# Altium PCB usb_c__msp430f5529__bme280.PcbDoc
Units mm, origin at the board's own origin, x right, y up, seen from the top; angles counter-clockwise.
Board outline 82 x 52 mm, 2 copper layers (Top, Bottom), stack 0 mm thick; 30 components, 24 nets, 182 pads, 58 vias.
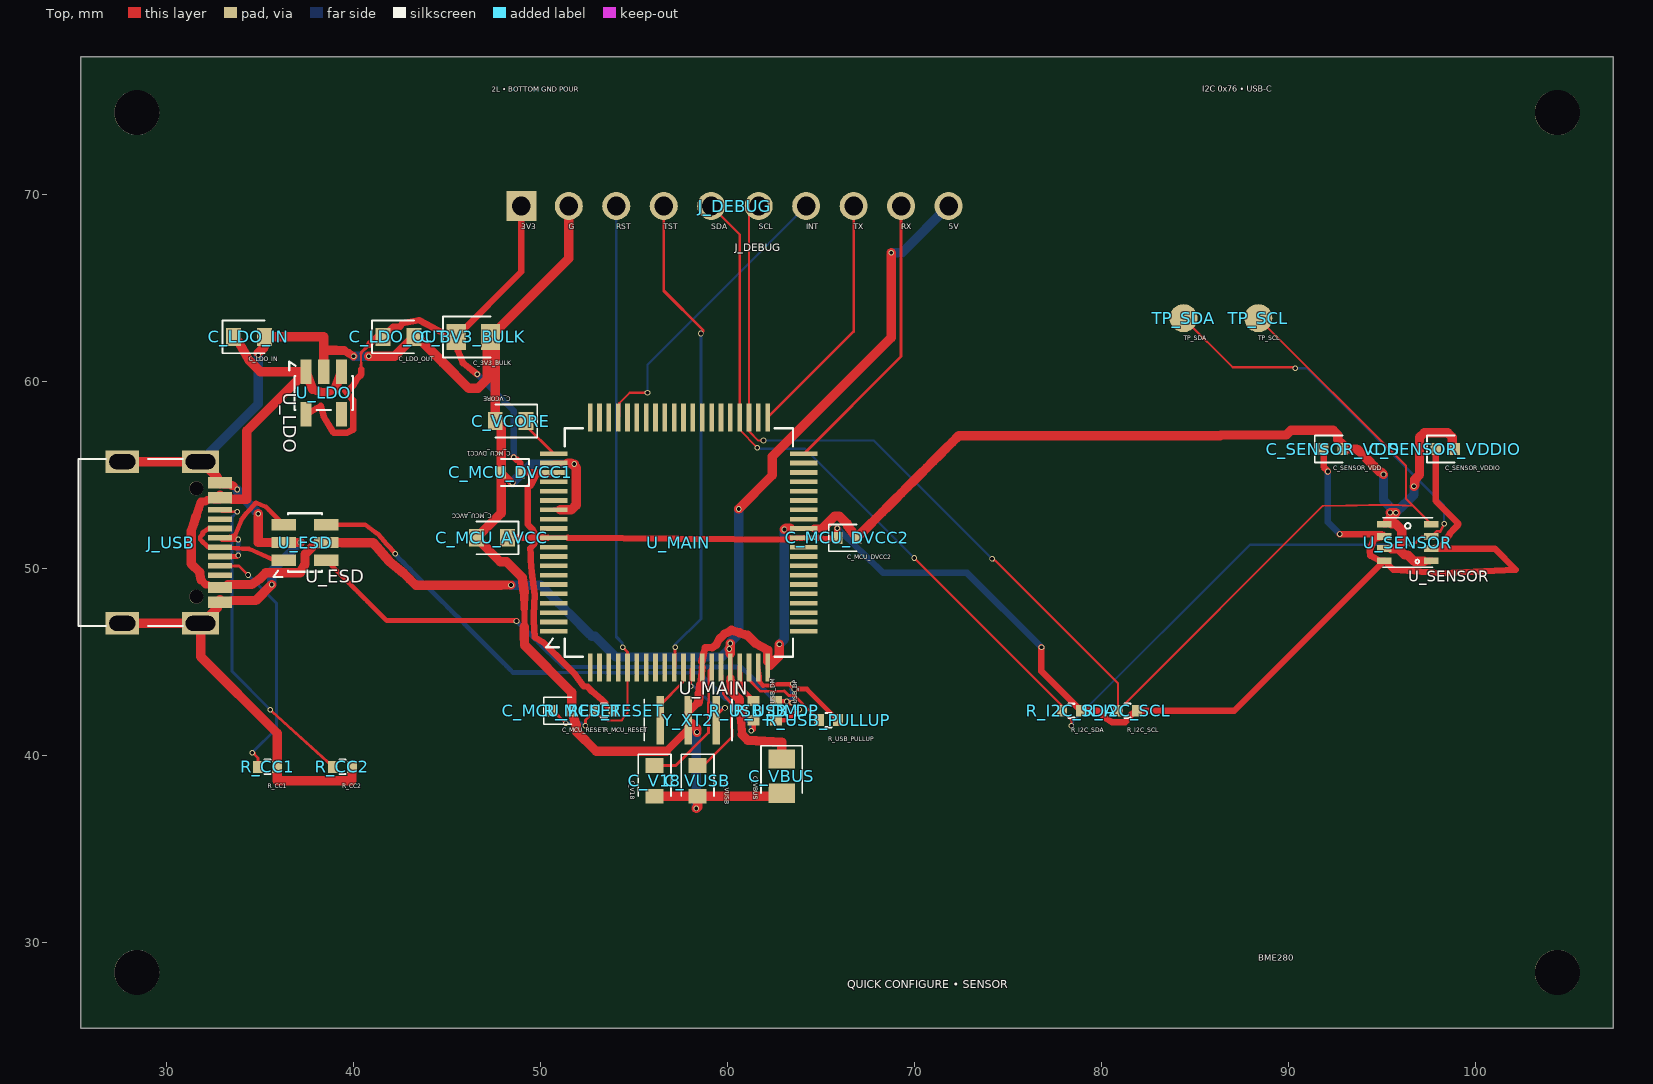
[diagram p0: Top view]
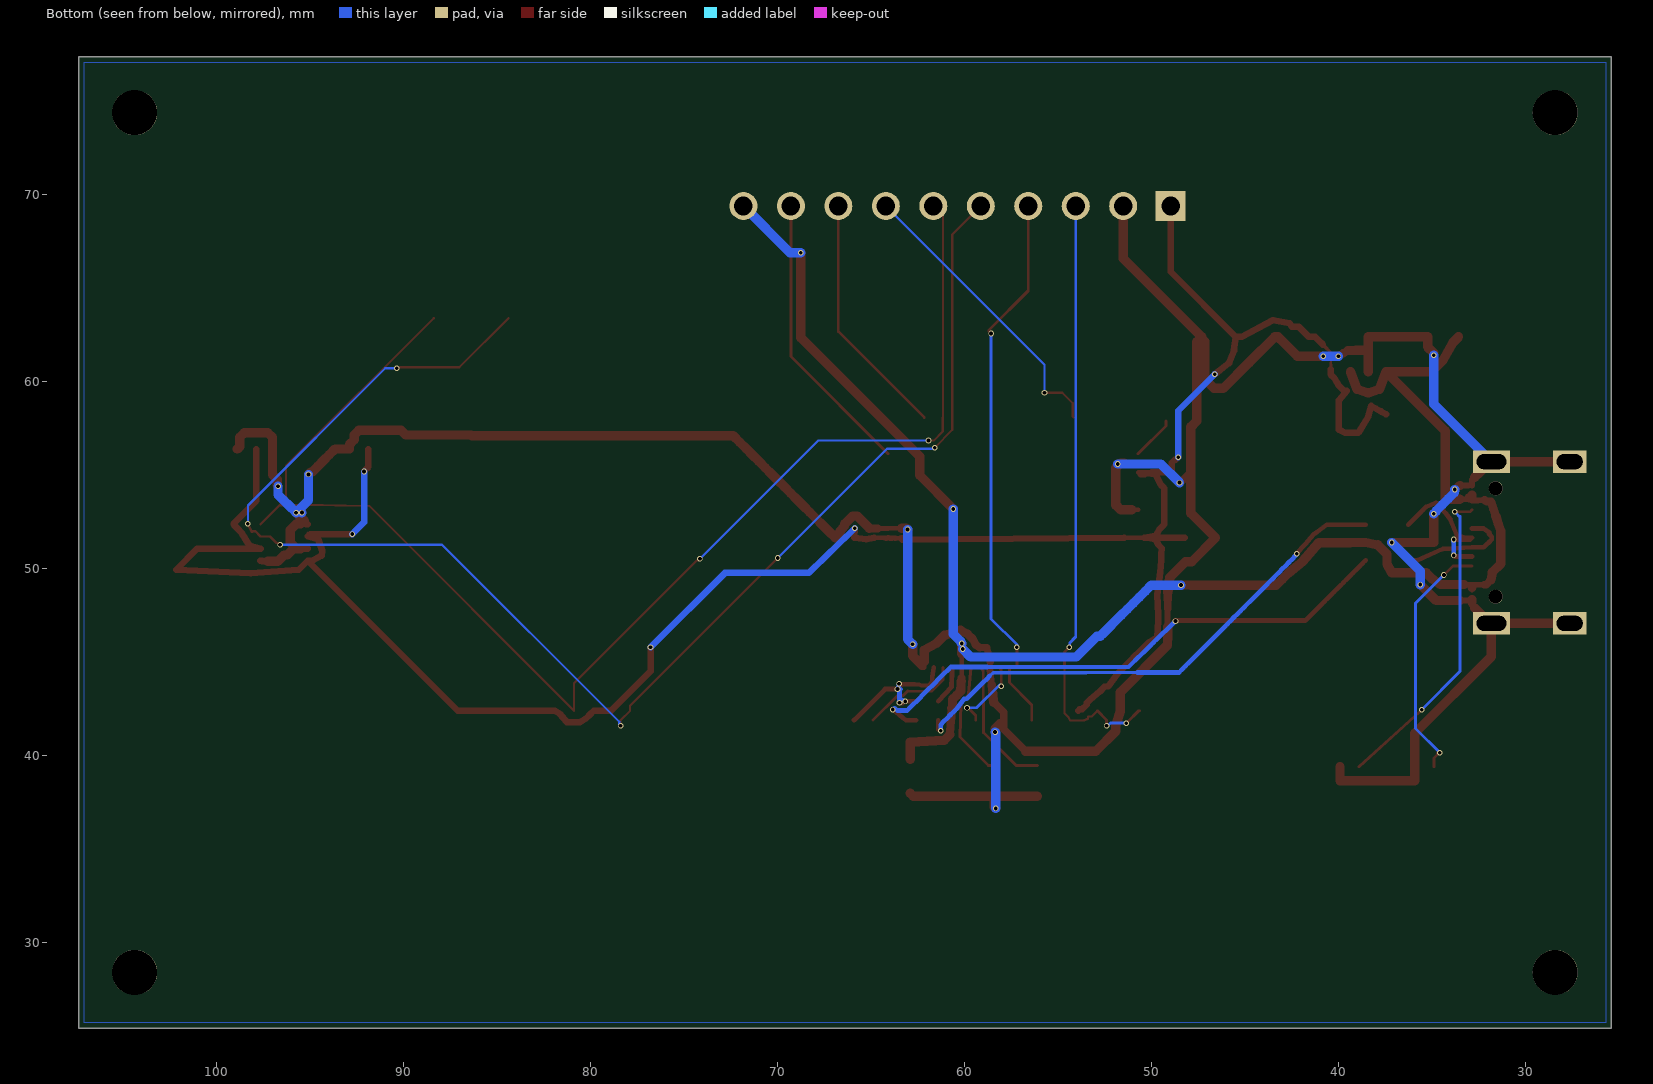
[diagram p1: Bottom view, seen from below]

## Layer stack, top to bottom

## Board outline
25.4,77.4 107.4,77.4 107.4,25.4 25.4,25.4

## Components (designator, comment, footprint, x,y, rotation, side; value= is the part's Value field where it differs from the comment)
C_3V3_BULK "" TSCIRCUIT-2.8500x1.4000mm 46.4,62.4 r0 top
C_LDO_IN "" TSCIRCUIT-2.4500x0.9500mm 34.4,62.4 r0 top
C_LDO_OUT "" TSCIRCUIT-2.4500x0.9500mm 42.4,62.4 r0 top
C_MCU_AVCC "" TSCIRCUIT-2.4500x0.9500mm 47.4,51.65 r180 top
C_MCU_DVCC1 "" TSCIRCUIT-1.5600x0.6400mm 48.4,55.15 r180 top
C_MCU_DVCC2 "" TSCIRCUIT-1.5600x0.6400mm 66.4,51.65 r0 top
C_MCU_RESET "" TSCIRCUIT-1.5600x0.6400mm 51.15,42.4 r0 top
C_SENSOR_VDD "" TSCIRCUIT-1.5600x0.6400mm 92.4,56.4 r0 top
C_SENSOR_VDDIO "" TSCIRCUIT-1.5600x0.6400mm 98.4,56.4 r0 top
C_V18 "" TSCIRCUIT-0.9500x2.4500mm 56.1,38.65 r270 top
C_VBUS "" TSCIRCUIT-1.4000x2.8500mm 62.9,38.9 r270 top
C_VCORE "" TSCIRCUIT-2.4500x0.9500mm 48.4,57.9 r180 top
C_VUSB "" TSCIRCUIT-0.9500x2.4500mm 58.4,38.65 r270 top
J_DEBUG "" TSCIRCUIT-24.3600x1.5000mm 60.4,69.4 r0 top
J_USB "" TSCIRCUIT-6.7732x9.8502mm 30.113,51.4 r90 top
R_CC1 "" TSCIRCUIT-1.5600x0.6400mm 35.4,39.4 r0 top
R_CC2 "" TSCIRCUIT-1.5600x0.6400mm 39.4,39.4 r0 top
R_I2C_SCL "" TSCIRCUIT-1.5600x0.6400mm 81.4,42.4 r0 top
R_I2C_SDA "" TSCIRCUIT-1.5600x0.6400mm 78.4,42.4 r0 top
R_MCU_RESET "" TSCIRCUIT-1.5600x0.6400mm 53.4,42.4 r0 top
R_USB_DM "" TSCIRCUIT-0.6400x1.5600mm 61.4,42.4 r90 top
R_USB_DP "" TSCIRCUIT-0.6400x1.5600mm 62.6,42.4 r90 top
R_USB_PULLUP "" TSCIRCUIT-1.5600x0.6400mm 65.4,41.9 r0 top
TP_SCL "" TSCIRCUIT-1.5000x1.5000mm 88.4,63.4 r0 top
TP_SDA "" TSCIRCUIT-1.5000x1.5000mm 84.4,63.4 r0 top
U_ESD "" TSCIRCUIT-3.6000x2.5000mm 37.4,51.4 r0 top
U_LDO "" TSCIRCUIT-2.5000x3.6000mm 38.4,59.4 r270 top
U_MAIN "" TSCIRCUIT-14.8500x14.8500mm 57.4,51.4 r0 top
U_SENSOR "" TSCIRCUIT-3.2841x2.3142mm 96.4,51.4 r0 top
Y_XT2 "" TSCIRCUIT-3.4000x2.6000mm 57.9,41.9 r270 top

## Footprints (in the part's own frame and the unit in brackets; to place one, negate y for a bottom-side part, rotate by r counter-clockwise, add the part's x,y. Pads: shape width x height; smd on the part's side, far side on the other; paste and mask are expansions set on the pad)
TSCIRCUIT-0.6400x1.5600mm [mm]
  rect 0.54x0.64 smd: 1(-0.51,0) 2(0.51,0)
  silkscreen extent -0.15,-0.38 0.15,0.38
TSCIRCUIT-0.9500x2.4500mm [mm]
  rect 0.8x0.95 smd: 1(-0.825,0) 2(0.825,0)
  silkscreen extent -1.43,-0.87 0.82,0.87
TSCIRCUIT-1.4000x2.8500mm [mm]
  rect 1.025x1.4 smd: 1(-0.913,0) 2(0.913,0)
  silkscreen extent -1.62,-1.1 0.91,1.1
TSCIRCUIT-1.5000x1.5000mm [mm]
  round 1.5 smd: 1(0,0)
TSCIRCUIT-1.5600x0.6400mm [mm]
  rect 0.54x0.64 smd: 1(-0.51,0) 2(0.51,0)
  silkscreen extent -0.98,-0.72 0.51,0.72
TSCIRCUIT-2.4500x0.9500mm [mm]
  rect 0.8x0.95 smd: 1(-0.825,0) 2(0.825,0)
  silkscreen extent -1.43,-0.87 0.82,0.87
TSCIRCUIT-2.5000x3.6000mm [mm]
  rect 1.325x0.6 smd: 1(-1.137,-0.95) 2(-1.137,0) 3(-1.137,0.95) 4(1.138,0.95) 5(1.138,-0.95)
  silkscreen extent -1.69,-1.84 0.91,1.56
TSCIRCUIT-2.8500x1.4000mm [mm]
  rect 1.025x1.4 smd: 1(-0.913,0) 2(0.913,0)
  silkscreen extent -1.63,-1.1 0.91,1.1
TSCIRCUIT-3.2841x2.3142mm [mm]
  rect 0.767x0.364 smd: 1(1.259,-0.975) 2(1.259,-0.325) 3(1.259,0.325) 4(1.259,0.975) 5(-1.259,0.975) 6(-1.259,0.325) 7(-1.259,-0.325) 8(-1.259,-0.975)
  silkscreen extent -1.33,-1.33 1.33,1.33
TSCIRCUIT-3.4000x2.6000mm [mm]
  rect 2.6x0.4 smd: 1(0,1.5) 2(0,0) 3(0,-1.5)
  silkscreen extent -1.1,-2.35 1.1,2.35
TSCIRCUIT-3.6000x2.5000mm [mm]
  rect 1.325x0.6 smd: 1(-1.137,-0.95) 2(-1.137,0) 3(-1.137,0.95) 4(1.138,0.95) 5(1.138,0) 6(1.138,-0.95)
  silkscreen extent -1.69,-1.84 0.91,1.56
TSCIRCUIT-6.7732x9.8502mm [mm]
  rect 0.3x1.3 smd: 1(-3.35,-2.737) 2(-3.05,-2.737) 3(-2.55,-2.737) 4(-2.25,-2.737) 5(-1.75,-2.737) 6(-1.25,-2.737) 7(-0.75,-2.737) 8(-0.25,-2.737) 9(0.25,-2.737) 10(0.75,-2.737) 11(1.25,-2.737) 12(1.75,-2.737) 13(2.55,-2.737) 14(2.25,-2.737) 15(3.35,-2.737) 16(3.05,-2.737)
  rect 1.2x2 hole 0.8 slot 1.6 at 90 deg: 17(-4.325,-1.693) 18(4.325,-1.693)
  rect 1.2x1.8 hole 0.8 slot 1.4 at 90 deg: 19(4.325,2.487) 20(-4.325,2.487)
  round 0.75 hole 0.75 unplated: NPTH-1(-2.9,-1.468) NPTH-2(2.9,-1.468)
  silkscreen extent -4.47,-0.75 4.47,4.83
TSCIRCUIT-14.8500x14.8500mm [mm]
  rect 1.475x0.25 smd: 1(-6.687,-4.75) 2(-6.687,-4.25) 3(-6.687,-3.75) 4(-6.687,-3.25) 5(-6.687,-2.75) 6(-6.687,-2.25) 7(-6.687,-1.75) 8(-6.687,-1.25) 9(-6.687,-0.75) 10(-6.687,-0.25) 11(-6.687,0.25) 12(-6.687,0.75) 13(-6.687,1.25) 14(-6.687,1.75) 15(-6.687,2.25) 16(-6.687,2.75) 17(-6.687,3.25) 18(-6.687,3.75) 19(-6.687,4.25) 20(-6.687,4.75) 41(6.687,4.75) 42(6.687,4.25) 43(6.687,3.75) 44(6.687,3.25) 45(6.687,2.75) 46(6.687,2.25) 47(6.687,1.75) 48(6.687,1.25) 49(6.687,0.75) 50(6.687,0.25) 51(6.687,-0.25) 52(6.687,-0.75) 53(6.687,-1.25) 54(6.687,-1.75) 55(6.687,-2.25) 56(6.687,-2.75) 57(6.687,-3.25) 58(6.687,-3.75) 59(6.687,-4.25) 60(6.687,-4.75)
  rect 0.25x1.475 smd: 21(-4.75,6.687) 22(-4.25,6.687) 23(-3.75,6.687) 24(-3.25,6.687) 25(-2.75,6.687) 26(-2.25,6.687) 27(-1.75,6.687) 28(-1.25,6.687) 29(-0.75,6.687) 30(-0.25,6.687) 31(0.25,6.687) 32(0.75,6.687) 33(1.25,6.687) 34(1.75,6.687) 35(2.25,6.687) 36(2.75,6.687) 37(3.25,6.687) 38(3.75,6.687) 39(4.25,6.687) 40(4.75,6.687) 61(4.75,-6.687) 62(4.25,-6.687) 63(3.75,-6.687) 64(3.25,-6.687) 65(2.75,-6.687) 66(2.25,-6.687) 67(1.75,-6.687) 68(1.25,-6.687) 69(0.75,-6.687) 70(0.25,-6.687) 71(-0.25,-6.687) 72(-0.75,-6.687) 73(-1.25,-6.687) 74(-1.75,-6.687) 75(-2.25,-6.687) 76(-2.75,-6.687) 77(-3.25,-6.687) 78(-3.75,-6.687) 79(-4.25,-6.687) 80(-4.75,-6.687)
  silkscreen extent -7.09,-6.11 6.11,6.11
TSCIRCUIT-24.3600x1.5000mm [mm]
  rect 1.6x1.6 hole 1: 1(-11.43,0)
  round 1.5 hole 1: 2(-8.89,0) 3(-6.35,0) 4(-3.81,0) 5(-1.27,0) 6(1.27,0) 7(3.81,0) 8(6.35,0) 9(8.89,0) 10(11.43,0)

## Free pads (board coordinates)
  round 2.4 hole 2.4 unplated: NPTH-3(28.4,28.4) NPTH-4(104.4,28.4) NPTH-5(28.4,74.4) NPTH-6(104.4,74.4)

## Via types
v1: diameter 0.3, hole 0.2, Top to Bottom, 58 vias

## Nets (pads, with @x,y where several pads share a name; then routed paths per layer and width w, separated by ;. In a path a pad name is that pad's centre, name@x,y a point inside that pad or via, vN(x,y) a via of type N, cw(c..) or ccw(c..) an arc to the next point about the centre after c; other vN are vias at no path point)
".J_DEBUG > .pin4 to .U_MAIN > .pin71": J_DEBUG.4 U_MAIN.71 | length 26.2
  Top w0.15: J_DEBUG.4 56.59,64.866 58.687,62.769 58.687,62.688 v1(58.58,62.581) ; U_MAIN.71 57.2,44.762 v1(57.2,45.8)
  Bottom w0.15: v1(57.2,45.8) 57.2,45.937 58.58,47.317 v1(58.58,62.581)
".J_DEBUG > .pin8 to .U_MAIN > .pin40": J_DEBUG.8 U_MAIN.40 | length 13.2
  Top w0.15: U_MAIN.40 66.75,62.687 J_DEBUG.8
".J_DEBUG > .pin9 to .U_MAIN > .pin41": J_DEBUG.9 U_MAIN.41 | length 15.4
  Top w0.15: U_MAIN.41 69.29,61.352 J_DEBUG.9
GND: C_3V3_BULK.2 C_LDO_IN.2 C_LDO_OUT.2 C_MCU_AVCC.2 C_MCU_DVCC1.2 C_MCU_DVCC2.2 C_MCU_RESET.2 C_SENSOR_VDD.2 C_SENSOR_VDDIO.2 C_V18.2 C_VBUS.2 C_VCORE.2 C_VUSB.2 J_DEBUG.2 J_USB.1 J_USB.2 J_USB.15 J_USB.16 J_USB.17 J_USB.18 J_USB.19 J_USB.20 R_CC1.2 R_CC2.2 U_ESD.2 U_LDO.2 U_MAIN.14 U_MAIN.19 U_MAIN.49 U_MAIN.61 U_MAIN.68 U_SENSOR.1 U_SENSOR.5 U_SENSOR.7 Y_XT2.2 | length 200.6
  Top w0.25: U_MAIN.14 U_MAIN.14@51.046,53.15 ; U_MAIN.68@58.619,45.025 U_MAIN.68 ; U_MAIN.61@62.15,45.034 U_MAIN.61 U_MAIN.61@62.275,44.837 ; U_MAIN.49@63.35,52.163 64.075,52.163 U_MAIN.49 64.181,52.15 64.275,52.15 64.369,52.15 64.462,52.15 64.556,52.15 U_MAIN.49@64.65,52.15 ; U_MAIN.19 51.45,55.65 51.369,55.65 51.275,55.65 51.181,55.65 51.088,55.65 50.994,55.65 50.9,55.65 50.806,55.65 U_MAIN.19
  Top w0.3: J_USB.1@32.699,47.9 J_USB.1 J_USB.2@32.849,48.2 ; 32.699,54.9 J_USB.15 J_USB.16@32.849,54.6 ; J_USB.2 33,48.252 33.125,48.296 33.499,48.296 ; J_USB.16 32.945,54.461 33.037,54.45 33.13,54.45 33.224,54.45 33.318,54.45 33.412,54.45 33.499,54.45
  Top w0.31: J_USB.16 J_USB.15@32.849,54.6
  Top w0.325: 33.55,54.45 33.585,54.415 33.761,54.241 v1(33.766,54.236) ; v1(34.89,61.421) v1@34.897,61.47 ; v1@48.426,54.614 v1(48.5,54.605) ; 49.131,47.862 49.132,47.374 49.134,46.887
  Top w0.364: U_SENSOR.5@95.525,52.4 95.233,52.4 95.208,52.375 U_SENSOR.5 ; U_SENSOR.1@97.275,50.4 97.567,50.4 97.592,50.425 U_SENSOR.1 ; U_SENSOR.7@95.133,51.067 U_SENSOR.7 U_SENSOR.7@95.133,51.067 ; U_SENSOR.7@95.133,51.067 95.525,51.067 U_SENSOR.7@95.133,51.067 ; U_SENSOR.5 95.323,52.557 U_SENSOR.5
  Top w0.375: 58.547,43.787 58.599,44.25 U_MAIN.68 ; U_MAIN.68@58.712,45.4 58.806,45.775 59.181,45.775
  Top w0.387: 49.13,48.349 49.131,47.862
  Top w0.396: U_MAIN.68@58.619,45.025 U_MAIN.68@58.712,45.4
  Top w0.4: v1@34.897,61.47 v1@34.897,61.536 ; C_MCU_DVCC1.2 48.158,54.882 v1@48.426,54.614 ; 56.733,40.233 57.9,41.4 Y_XT2.2 ; Y_XT2.2@58.1,41.7 Y_XT2.2 ; 58.444,42.862 57.9,42.318 Y_XT2.2
  Top w0.437: 39.494,61.681 39.745,61.524 v1(39.996,61.367) ; 59.181,45.775 59.4,45.931 59.546,46.223
  Top w0.45: 33.505,54.45 33.55,54.45 ; 58.496,43.325 58.547,43.787 ; 59.546,46.223 59.838,46.515 59.977,46.573 ; U_MAIN.49@64.65,52.15 65.087,52.166
  Top w0.475: 33.499,54.45 33.505,54.45 ; 39.056,61.681 39.494,61.681 ; 49.126,48.725 49.13,48.349 ; 59.977,46.573 60.213,46.712 60.643,46.573
  Top w0.5: J_USB.20 J_USB.17 ; J_USB.19 J_USB.18 31.874,55.725 32.474,55.125 32.699,54.9 ; J_USB.1@32.699,47.9 32.474,47.675 31.874,47.075 J_USB.17 ; J_USB.1@32.849,48.2 J_USB.2 ; 33.499,48.296 34.771,48.296 v1(35.624,49.149) ; v1(34.891,52.94) 34.891,51.4 U_ESD.2 ; v1@34.897,61.536 35.225,61.865 35.225,62.132 C_LDO_IN.2 38.4,62.4 U_LDO.2 38.4,61.681 39.056,61.681 ; U_ESD.2 v1(37.147,51.4) ; R_CC2.2 39.91,38.65 35.91,38.65 R_CC1.2 35.91,41.198 31.812,45.296 31.812,47.068 J_USB.17 ; v1(40.804,61.361) 40.809,61.366 40.903,61.366 41.333,61.366 41.762,61.366 42.191,61.366 42.536,61.711 42.88,62.055 C_LDO_OUT.2 43.4,62.4 44.775,61.025 46.15,59.65 46.65,59.65 47.15,60.15 47.15,62.15 47.4,62.4 C_3V3_BULK.2 ; 49.126,48.725 49.025,49.525 48.174,50.376 47.849,50.376 C_MCU_AVCC.2 47.89,52.965 C_MCU_DVCC1.2 47.89,57.585 C_VCORE.2 47.575,62.138 C_3V3_BULK.2 ; 49.134,46.887 49.135,46.399 49.136,45.912 51.66,43.388 C_MCU_RESET.2 51.9,41.65 51.9,41.317 52.983,40.233 56.733,40.233 ; U_MAIN.14@51.046,53.15 51.65,53.15 51.9,53.4 51.9,55.4 51.65,55.65 51.45,55.65 51.463,55.65 51.642,55.65 51.692,55.6 v1(51.8,55.6) ; J_DEBUG.2 51.51,66.597 C_3V3_BULK.2 ; C_V18.2 C_VUSB.2 ; 58.1,41.7 58.366,41.434 v1(58.366,41.258) ; v1(58.327,37.175) 58.4,37.248 C_VUSB.2 ; 58.444,42.862 58.496,43.325 ; 60.643,46.573 61.073,46.433 61.191,46.315 61.511,45.996 62.15,45.65 U_MAIN.61@62.15,45.034 ; 62.275,44.837 62.778,45.341 v1(62.778,45.955) ; C_VBUS.2 62.737,37.825 C_VUSB.2 ; v1(63.045,52.096) 63.112,52.163 63.337,52.163 63.35,52.163 ; 65.087,52.166 65.416,52.494 65.744,52.822 65.978,52.822 66.4,52.4 66.424,52.285 66.667,51.968 C_MCU_DVCC2.2 67.251,51.991 67.592,52.332 67.933,52.673 68.274,53.014 68.615,53.355 68.956,53.696 69.297,54.037 69.637,54.377 69.978,54.718 70.319,55.059 70.66,55.4 71.001,55.741 71.342,56.082 71.683,56.423 72.024,56.764 72.365,57.105 72.854,57.105 73.342,57.105 73.831,57.105 74.32,57.105 74.808,57.105 75.297,57.105 75.786,57.105 76.274,57.105 76.763,57.105 77.252,57.105 77.74,57.105 78.229,57.105 78.718,57.105 79.206,57.105 79.695,57.105 80.184,57.105 80.672,57.105 81.161,57.105 81.649,57.105 82.138,57.105 82.627,57.105 83.115,57.105 83.604,57.105 84.093,57.105 84.581,57.105 85.07,57.105 85.559,57.105 86.047,57.105 86.355,57.105 86.4,57.15 89.9,57.15 90.15,57.4 92.4,57.4 92.65,57.15 92.65,56.9 92.9,56.65 92.9,56.4 C_SENSOR_VDD.2 93.291,56.4 93.673,56.4 93.98,56.093 94.287,55.786 94.594,55.479 94.901,55.172 94.966,55.172 v1(95.096,55.042) ; v1(95.45,53) v1@95.759,52.993 ; U_SENSOR.5@95.525,52.4 95.733,52.4 96.067,52.067 96.067,51.4 95.733,51.067 95.525,51.067 95.9,51.067 96.233,50.733 96.4,50.733 96.733,50.4 U_SENSOR.1@97.275,50.4 ; v1(96.724,54.413) 96.775,54.464 96.775,54.775 97.025,55.025 97.025,57.025 97.275,57.275 98.525,57.275 98.775,57.025 98.775,56.525 98.9,56.4 C_SENSOR_VDDIO.2 ; 95.45,52.684 95.323,52.557 95.45,52.684 ; 95.45,52.684 v1@95.759,52.993 ; 95.45,52.684 v1@95.759,52.993
  Bottom w0.5: J_USB.18 34.89,58.809 v1(34.89,61.421) ; v1(33.766,54.236) 33.8,54.063 34.121,53.742 34.442,53.421 34.763,53.1 34.763,53.068 v1(34.891,52.94) ; v1(35.624,49.149) 35.624,49.877 v1(37.147,51.4) ; v1(39.996,61.367) 39.999,61.364 40.057,61.364 40.06,61.361 40.432,61.361 v1(40.804,61.361) ; v1(48.5,54.605) 49.495,55.6 v1(51.8,55.6) ; v1(58.327,37.175) 58.327,41.114 58.327,41.219 v1(58.366,41.258) ; v1(62.778,45.955) 63.045,46.222 v1(63.045,52.096) ; v1(95.096,55.042) 95.096,54.58 95.096,54.118 95.096,53.657 95.401,53.351 95.707,53.046 v1(95.45,53) ; v1(95.76,52.993) 95.811,53.045 96.116,53.349 96.42,53.653 96.724,53.957 v1(96.724,54.413)
MAIN_RESET: C_MCU_RESET.1 J_DEBUG.3 R_MCU_RESET.1 U_MAIN.76 | length 32.7
  Top w0.12: R_MCU_RESET.1 53.2,42.09 53.384,42.09 53.396,41.972 53.596,41.892 53.996,41.877 54.357,41.873 54.432,42.053 54.65,42.27 U_MAIN.76
  Top w0.15: C_MCU_RESET.1 50.678,42.4 51.316,41.762 v1(51.342,41.736) ; v1(52.4,41.6) 52.4,41.91 R_MCU_RESET.1 ; v1(54.4,45.8) 54.65,45.55 U_MAIN.76
  Bottom w0.15: v1(51.342,41.736) 52.193,41.736 52.298,41.631 52.369,41.631 v1(52.4,41.6) ; J_DEBUG.3 54.05,46.356 54.372,46.033 54.372,45.828 v1(54.4,45.8)
MSP_USB_PUR: R_USB_PULLUP.1 U_MAIN.63 | length 5.3
  Top w0.15: U_MAIN.63 61.15,44.058 61.748,43.46 62.006,43.429 63.036,43.46 63.278,43.219 63.571,43.219 R_USB_PULLUP.1
MSP_V18: C_V18.1 U_MAIN.67 | length 7.2
  Top w0.15: C_V18.1 57.23,39.475 58.906,41.15 58.983,41.218 58.995,44.536 U_MAIN.67
MSP_VCORE: C_VCORE.1 U_MAIN.20 | length 2.4
  Top w0.15: C_VCORE.1 49.225,57.638 U_MAIN.20
MSP_VUSB: C_VUSB.1 U_MAIN.66 | length 6.3
  Top w0.15: C_VUSB.1 58.727,39.475 60.24,40.989 60.195,42.808 59.907,43.118 59.786,43.3 U_MAIN.66
SENSOR_INT: J_DEBUG.7 U_MAIN.24 | length 16
  Top w0.12: U_MAIN.24 54.207,58.144 54.207,58.848 54.774,59.415 v1(55.721,59.415)
  Bottom w0.12: v1(55.721,59.415) 55.723,59.417 55.723,60.913 J_DEBUG.7
SENSOR_SCL: J_DEBUG.6 R_I2C_SCL.1 TP_SCL.1 U_MAIN.38 U_SENSOR.4 | length 75.6
  Top w0.12: J_DEBUG.6 61.15,68.88 U_MAIN.38 61.16,58.077 61.16,57.343 61.653,56.851 v1(61.929,56.859) ; v1(74.156,50.53) 74.255,50.431 74.327,50.431 80.89,43.869 R_I2C_SCL.1 91.85,53.36 95.525,53.421 96.674,53.36 U_SENSOR.4 96.294,53.74 96.294,53.809 96.294,55.506 TP_SCL.1
  Bottom w0.12: v1(61.929,56.859) 62.025,56.851 67.835,56.851 v1(74.156,50.53)
SENSOR_SDA: J_DEBUG.5 R_I2C_SDA.1 TP_SDA.1 U_MAIN.37 U_SENSOR.3 | length 81
  Top w0.12: J_DEBUG.5 60.65,67.88 U_MAIN.37 60.65,57.426 v1(61.59,56.471) ; v1(69.994,50.571) 70.129,50.436 ; 70.13,50.436 77.89,42.676 R_I2C_SDA.1 78.4,41.89 v1(78.4,41.6) ; TP_SDA.1 87.029,60.771 90.311,60.771 90.328,60.771 v1(90.377,60.722) ; v1(96.616,51.285) 96.702,51.371 96.805,51.371 97.159,51.725 U_SENSOR.3 97.937,52.003 98.042,52.003 ; 98.042,52.004 98.116,51.956 v1(98.345,52.397)
  Bottom w0.12: v1(61.59,56.471) 61.663,56.413 61.665,56.413 64.152,56.413 v1(69.994,50.571) ; v1(78.4,41.6) 78.469,41.669 78.469,41.806 87.948,51.285 v1(96.616,51.285) ; v1(90.377,60.722) 90.996,60.722 98.336,53.382 98.336,52.453 98.306,52.423 v1(98.345,52.397)
usb-dm-mcu: R_USB_DM.2 U_MAIN.64 | length 2.1
  Top w0.25: U_MAIN.64 60.698,43.67 R_USB_DM.2
usb-dm-phy: R_USB_DM.1 U_ESD.4 | length 28.2
  Top w0.25: U_ESD.4 38.786,52.35 39.016,52.35 39.247,52.35 39.477,52.35 39.707,52.35 39.938,52.35 40.168,52.35 40.399,52.35 40.629,52.35 40.804,52.218 40.978,52.086 41.153,51.955 41.327,51.823 41.477,51.653 41.627,51.483 41.777,51.313 41.927,51.144 42.077,50.974 v1(42.227,50.804) ; v1(61.276,41.325) 61.346,41.395 61.39,41.395 61.4,41.405 61.4,41.647 R_USB_DM.1
  Bottom w0.185: 50.763,44.446 51.011,44.446 51.26,44.446 51.509,44.445 51.757,44.445 52.006,44.445 52.255,44.445 52.503,44.445 52.752,44.445 53.001,44.445 53.249,44.445 53.498,44.444 53.746,44.444 53.995,44.444 54.244,44.444 54.492,44.444 54.741,44.444 54.99,44.444 55.238,44.444 55.487,44.443 55.736,44.443 55.984,44.443 56.233,44.443 56.482,44.443 56.73,44.443 56.979,44.443 57.228,44.443 57.476,44.443 57.725,44.442 57.974,44.442 58.222,44.442 58.471,44.442 58.646,44.268
  Bottom w0.25: v1(42.227,50.804) 42.298,50.681 42.472,50.508 42.645,50.334 42.818,50.161 42.991,49.988 43.164,49.815 43.337,49.642 43.51,49.469 43.683,49.295 43.856,49.122 44.028,48.949 44.201,48.776 44.374,48.603 44.547,48.43 44.72,48.256 44.893,48.083 45.066,47.91 45.239,47.737 45.412,47.564 45.585,47.391 45.758,47.217 45.931,47.044 46.104,46.871 46.277,46.698 46.45,46.525 46.623,46.352 46.795,46.178 46.968,46.005 47.141,45.832 47.314,45.659 47.487,45.486 47.66,45.313 47.833,45.139 48.006,44.966 48.179,44.793 48.352,44.62 48.525,44.447 48.773,44.447 49.022,44.447 49.271,44.446 49.519,44.446 49.768,44.446 50.017,44.446 50.265,44.446 50.514,44.446 50.763,44.446 ; 58.646,44.268 58.822,44.093 58.998,43.919 59.173,43.744 59.349,43.57 59.524,43.395 59.7,43.221 59.875,43.047 60.025,43.025 60.402,42.523 60.578,42.349 60.753,42.174 60.929,42 61.105,41.826 61.28,41.651 61.278,41.488 v1(61.276,41.325)
usb-dm-port: J_USB.7 J_USB.9 U_ESD.3 | length 7.9
  Top w0.25: J_USB.7 33.767,50.65 33.825,50.708 v1(33.827,50.71) ; v1(33.832,51.56) 32.939,51.56 J_USB.9 33.035,51.65 33.221,51.65 33.65,51.775 34.025,52.65 33.981,52.598 34.112,52.775 34.243,52.953 34.775,53.525 35.313,53.3 35.471,53.142 35.629,52.984 35.788,52.825 35.946,52.667 36.104,52.508 U_ESD.3
  Bottom w0.25: v1(33.827,50.71) 33.827,51.428 33.849,51.45 33.849,51.543 v1(33.832,51.56)
usb-dp-mcu: R_USB_DP.2 R_USB_PULLUP.2 U_MAIN.62 | length 10.1
  Top w0.225: 62.3,43.75 62.44,43.811 62.662,43.812
  Top w0.238: 61.9,43.75 62.1,43.75 62.3,43.75
  Top w0.25: U_MAIN.62 61.719,44.191 61.719,43.966 61.7,43.975 61.8,43.863 61.9,43.75 ; 62.662,43.812 62.885,43.812 63.107,43.812 63.33,43.812 63.456,43.685 v1(63.5,43.85) ; v1(63.175,42.9) 63.472,42.82 63.313,42.82 63.222,42.91 63.015,42.91 62.807,42.91 R_USB_DP.2 63.216,42.91 63.311,42.815 63.467,42.815 v1(63.476,42.824) ; v1(63.583,43.559) 64.251,43.559 R_USB_PULLUP.2
  Bottom w0.25: v1(63.175,42.9) 63.476,43.051 63.476,43.278 63.476,43.505 63.428,43.553 63.577,43.553 v1(63.5,43.85) ; v1(63.476,42.824) 63.476,43.452 63.561,43.537 v1(63.583,43.559)
usb-dp-phy: R_USB_DP.1 U_ESD.6 | length 30.2
  Top w0.25: U_ESD.6 38.707,50.28 38.877,50.111 39.047,49.941 39.216,49.771 39.386,49.601 39.556,49.432 39.726,49.262 39.895,49.092 40.065,48.922 40.235,48.753 40.405,48.583 40.574,48.413 40.744,48.243 40.914,48.074 41.084,47.904 41.253,47.734 41.423,47.564 41.593,47.395 41.763,47.225 42.011,47.225 42.258,47.225 42.506,47.225 42.754,47.225 43.002,47.225 43.249,47.225 43.497,47.225 43.745,47.225 43.993,47.225 44.241,47.225 44.488,47.225 44.736,47.225 44.984,47.225 45.232,47.225 45.48,47.225 45.727,47.225 45.975,47.225 46.223,47.225 46.471,47.225 46.718,47.225 46.966,47.225 47.214,47.225 47.462,47.225 47.71,47.225 47.957,47.225 48.205,47.225 48.453,47.225 48.701,47.225 48.737,47.225 v1(48.713,47.196) ; R_USB_DP.1 62.777,41.89 62.954,41.89 63.131,41.89 63.308,42.033 63.486,42.175 63.663,42.318 v1(63.84,42.46)
  Bottom w0.212: 50.895,45.072 51.063,44.909 51.231,44.746 51.475,44.745 51.719,44.745 51.962,44.745 52.206,44.745 52.45,44.745 52.694,44.745 52.938,44.745 53.182,44.745 53.426,44.744 53.67,44.744 53.914,44.744 54.158,44.744 54.401,44.744 54.645,44.744 54.889,44.744 55.133,44.744 55.377,44.744 55.621,44.743 55.865,44.743 56.109,44.743 56.353,44.743 56.597,44.743 56.84,44.743 57.084,44.743 57.328,44.743 57.572,44.742 57.816,44.742 58.06,44.742 58.304,44.742 58.548,44.742
  Bottom w0.225: 58.548,44.742 58.792,44.742
  Bottom w0.25: v1(48.713,47.196) 48.881,47.033 49.049,46.869 49.216,46.706 49.384,46.542 49.552,46.379 49.72,46.216 49.888,46.052 50.056,45.889 50.224,45.726 50.391,45.562 50.559,45.399 50.727,45.236 50.895,45.072 ; 58.792,44.742 59.035,44.742 59.279,44.742 59.523,44.742 59.767,44.741 60.011,44.741 60.255,44.741 60.499,44.741 60.743,44.741 60.908,44.575 61.074,44.408 61.24,44.242 61.406,44.075 61.571,43.909 61.737,43.743 61.903,43.576 62.068,43.41 62.234,43.243 62.4,43.077 62.565,42.911 62.731,42.744 62.897,42.578 63.063,42.411 63.296,42.411 63.53,42.411 63.6,42.411 63.726,42.538 63.763,42.538 v1(63.84,42.46)
usb-dp-port: J_USB.8 J_USB.10 U_ESD.1 | length 6.2
  Top w0.25: J_USB.10 32.644,52.15 32.44,52.15 32.235,52.15 31.9,51.9 31.945,51.86 31.8,51.715 31.8,51.561 31.938,51.423 32.076,51.285 32.214,51.147 32.425,51.147 32.635,51.147 32.846,51.147 J_USB.8 34.422,51.054 35.764,50.451 U_ESD.1@36.262,50.451
USB_CC1: J_USB.6 R_CC1.1 | length 13.3
  Top w0.15: J_USB.6 33.868,50.15 v1(34.354,49.664) ; v1(34.569,40.154) 34.69,40.135 34.69,40.067 34.89,39.867 R_CC1.1
  Bottom w0.15: v1(34.354,49.664) 34.451,49.567 34.454,49.567 35.869,48.153 35.874,41.453 v1(34.569,40.154)
USB_CC2: J_USB.12 R_CC2.1 | length 17.1
  Top w0.15: J_USB.12 32.958,53.041 v1(33.779,53.041) ; v1(35.533,42.459) 35.635,42.365 R_CC2.1
  Bottom w0.15: v1(33.779,53.041) 33.684,52.946 33.678,52.946 33.539,52.807 33.487,52.807 33.487,44.513 v1(35.533,42.459)
VBUS5: C_LDO_IN.1 C_VBUS.1 J_DEBUG.10 J_USB.3 J_USB.4 J_USB.13 J_USB.14 U_ESD.5 U_LDO.1 U_LDO.3 U_MAIN.65 | length 94
  Top w0.25: U_MAIN.65@60.15,44.15 U_MAIN.65 ; U_MAIN.65 60.15,45.45 U_MAIN.65
  Top w0.275: J_USB.3 J_USB.4@32.849,49
  Top w0.3: 32.181,53.666 32.536,53.65 J_USB.14 32.849,53.8 ; J_USB.4@32.199,49.15 J_USB.4 ; J_USB.3@32.849,49 J_USB.4 ; J_USB.13 32.989,53.8 33.064,53.721 33.499,53.721 ; J_USB.4@33.274,49.15 J_USB.4
  Top w0.4: 31.838,49.4 32.087,49.15 J_USB.4@32.199,49.15
  Top w0.431: U_MAIN.65@60.15,44.15 U_MAIN.65@60.172,43.975
  Top w0.437: 31.706,53.194 31.838,53.588 32.056,53.588 32.181,53.666
  Top w0.45: 31.575,52.8 31.706,53.194 ; 60.676,42.541 60.713,42.067 60.749,41.593 60.785,41.119
  Top w0.475: J_USB.13@32.849,53.8 J_USB.13 ; J_USB.4@33.274,49.15 33.699,49.15 ; 47.888,49.12 48.343,49.121 v1(48.417,49.121) ; 60.785,41.119 61.077,40.827
  Top w0.5: 31.575,52.8 31.444,52.406 31.313,52.012 31.313,50.256 31.761,49.807 31.838,49.4 ; 33.499,53.721 34.282,53.721 34.29,53.713 34.29,57.377 U_LDO.1 ; C_LDO_IN.1 33.87,62.105 33.87,62.094 34.4,61.15 35.013,60.537 U_LDO.1 ; 33.699,49.15 34.124,49.15 34.548,49.15 34.959,49.431 35.302,49.775 37.15,49.775 37.4,50.275 37.4,50.775 37.9,51.275 U_ESD.5 38.956,51.397 39.374,51.395 39.793,51.392 40.211,51.389 40.63,51.387 41.048,51.384 41.9,50.4 42.68,49.76 43.007,49.436 43.333,49.111 43.789,49.112 44.244,49.113 44.7,49.114 45.155,49.115 45.61,49.116 46.066,49.117 46.521,49.117 46.977,49.118 47.432,49.119 47.888,49.12 ; U_LDO.3 39,59.6 38.4,59.4 37.8,59.6 U_LDO.1 ; v1(60.1,45.7) 60.15,45.65 60.15,45.45 v1(60.15,46) ; U_MAIN.65@60.172,43.975 60.185,43.872 60.202,43.452 60.421,43.233 60.64,43.015 60.64,42.577 60.676,42.541 ; v1(60.599,53.193) 62.4,54.994 62.4,56 68.761,62.361 68.761,62.935 68.761,63.431 68.761,63.927 68.761,64.424 68.761,64.92 68.761,65.416 68.761,65.912 68.761,66.409 v1(68.761,66.905) ; 61.077,40.827 61.533,40.801 61.989,40.775 62.444,40.75 62.9,40.724 62.9,40.268 C_VBUS.1
  Bottom w0.5: v1(48.417,49.121) 48.814,49.121 49.211,49.121 49.608,49.121 50.005,49.121 50.329,48.798 50.652,48.474 50.975,48.151 51.299,47.828 51.622,47.504 51.945,47.181 52.269,46.858 52.592,46.534 52.592,46.531 52.735,46.388 52.912,46.388 54.025,45.275 59.675,45.275 v1(60.1,45.7) ; v1(60.15,46) 60.205,46.055 60.205,46.109 60.402,46.306 60.599,46.503 60.599,46.981 60.599,47.459 60.599,47.936 60.599,48.414 60.599,48.892 60.599,49.37 60.599,49.848 60.599,50.326 60.599,50.804 60.599,51.282 60.599,51.759 60.599,52.237 60.599,52.715 v1(60.599,53.193) ; v1(68.761,66.905) 69.335,66.905 J_DEBUG.10
VCC_3V3: C_3V3_BULK.1 C_LDO_OUT.1 C_MCU_AVCC.1 C_MCU_DVCC1.1 C_MCU_DVCC2.1 C_SENSOR_VDD.1 C_SENSOR_VDDIO.1 J_DEBUG.1 R_I2C_SCL.2 R_I2C_SDA.2 R_MCU_RESET.2 U_LDO.5 U_MAIN.11 U_MAIN.18 U_MAIN.50 U_SENSOR.2 U_SENSOR.6 U_SENSOR.8 | length 135.7
  Top w0.12: 40.39,61.48 40.397,61.207 40.403,60.935
  Top w0.15: 40.39,61.48 40.416,61.576 40.622,61.782
  Top w0.162: 40.403,60.935 40.41,60.662
  Top w0.2: 40.622,61.782 40.829,61.988
  Top w0.25: U_MAIN.18@49.975,55.075 U_MAIN.18@50.125,55.075 ; U_MAIN.18@49.975,55.15 50.056,55.15 50.15,55.15 50.244,55.15 50.337,55.15 50.431,55.15 50.525,55.15 50.619,55.15 U_MAIN.18 U_MAIN.18@50.588,55.025 ; U_MAIN.11@49.976,51.65 50.057,51.65 50.15,51.65 50.244,51.65 50.338,51.65 50.432,51.65 50.525,51.65 50.619,51.65 U_MAIN.11 ; U_MAIN.11@50.236,51.65 50.474,51.65 U_MAIN.11 ; U_MAIN.11@50.371,51.65 U_MAIN.11 ; 51.45,51.65 51.369,51.65 51.275,51.65 51.181,51.65 51.088,51.65 50.994,51.65 50.9,51.65 50.806,51.65 U_MAIN.11 ; U_MAIN.50@63.988,51.619 U_MAIN.50 ; U_MAIN.50@64.278,51.642 64.369,51.65 64.463,51.65 64.557,51.65 64.651,51.65 64.744,51.65 U_MAIN.50@64.825,51.65
  Top w0.252: U_MAIN.50@63.429,51.63 63.523,51.633 U_MAIN.50@63.617,51.633
  Top w0.257: U_MAIN.50@63.617,51.633 U_MAIN.50@63.71,51.633
  Top w0.279: U_MAIN.50@63.71,51.633 63.805,51.635 U_MAIN.50@63.899,51.637
  Top w0.288: U_MAIN.18@50.125,55.075 50.331,55.051 50.349,55.023 50.585,55.023 U_MAIN.18@50.587,55.025 ; U_MAIN.50@63.899,51.637 U_MAIN.50@63.988,51.619 ; U_MAIN.50 64.188,51.618 U_MAIN.50@64.278,51.642
  Top w0.301: 63.348,51.62 U_MAIN.50@63.429,51.63
  Top w0.35: U_LDO.5 37.717,58.41 37.984,58.557 38.251,58.704 38.4,58.138 38.925,57.262 39.625,57.262 39.975,57.438 39.975,59.013 39.539,59.513 39.6,59.5 39.625,59.45 39.975,59.8 40.197,60.171 40.416,60.39 40.41,60.662 ; 40.829,61.988 41.035,62.194 41.241,62.4 C_LDO_OUT.1 41.76,62.585 41.945,62.77 42.13,62.955 42.311,62.955 42.491,62.955 42.493,62.955 42.6,63.125 43.475,63.3 45.184,62.4 C_3V3_BULK.1 ; v1(46.607,60.405) 45.85,61 45.584,61.663 C_3V3_BULK.1 ; C_MCU_AVCC.1 49.963,51.65 49.975,51.65 ; v1(48.571,55.956) 48.695,55.832 48.746,55.832 48.91,55.668 C_MCU_DVCC1.1 49.963,55.15 U_MAIN.18@49.975,55.15 ; J_DEBUG.1 48.97,65.882 C_3V3_BULK.1 ; 49.975,55.075 49.775,55.075 49.508,54.51 49.312,54.314 49.312,53.99 49.312,53.666 49.312,53.341 49.312,53.017 49.312,52.693 49.312,52.368 49.551,52.129 49.775,51.75 U_MAIN.11@50.371,51.65 ; U_MAIN.11@50.236,51.65 49.775,51.575 49.634,51.28 49.452,51.095 49.468,50.772 49.484,50.45 49.5,50.127 49.516,49.804 49.688,48.6 49.628,47.545 49.644,47.223 49.688,46.325 50.17,46.034 50.405,45.797 50.64,45.561 50.875,45.325 51.11,45.088 51.345,44.852 51.581,44.615 51.816,44.379 52.312,43.7 52.521,43.67 52.756,43.434 53.275,43 53.45,42.825 53.462,42.724 53.697,42.488 53.822,42.488 R_MCU_RESET.2 ; 51.45,51.65 51.462,51.648 63.338,51.554 63.348,51.62 ; 64.825,51.65 64.838,51.65 65.253,51.586 C_MCU_DVCC2.1 65.87,52.129 65.876,52.135 v1(65.875,52.162) ; v1(76.798,45.798) 76.798,44.512 R_I2C_SDA.2 79.218,42.4 79.526,42.4 79.833,42.4 80.037,42.196 80.241,41.992 80.575,41.775 81.275,41.775 81.657,42.237 R_I2C_SCL.2 87.116,42.4 U_SENSOR.8 ; C_SENSOR_VDD.1 91.89,55.442 92.096,55.236 92.096,55.223 v1(92.122,55.197) ; v1(92.75,51.852) 95.014,51.852 U_SENSOR.6 94.575,51.575 94.363,50.967 94.4,50.7 94.905,50.425 U_SENSOR.8 ; C_SENSOR_VDDIO.1 97.89,56.053 97.89,55.706 97.89,55.358 97.89,55.011 97.89,54.664 97.89,54.317 97.89,53.97 97.89,53.623 98.133,53.38 98.375,53.137 98.618,52.895 98.861,52.652 99.103,52.409 99.103,52.367 98.894,52.148 98.684,51.929 98.25,51.225 U_SENSOR.2 101.046,51.075 102.177,49.944 98.195,49.754 95.623,49.944 U_SENSOR.8
  Bottom w0.35: v1(46.607,60.405) 46.637,60.379 48.571,58.445 v1(48.571,55.956) ; v1(65.875,52.162) 68.335,49.775 72.614,49.775 72.821,49.775 76.74,45.856 v1(76.798,45.798) ; v1(92.122,55.197) 92.122,52.49 92.681,51.93 92.681,51.921 v1(92.75,51.852)
XT2_IN: U_MAIN.69 Y_XT2.1 | length 4.3
  Top w0.15: v1(58.034,43.714) 58.034,44.596 U_MAIN.69 ; Y_XT2.1 59.4,42.152 59.752,42.504 59.818,42.504 v1(59.866,42.552)
  Bottom w0.15: v1(58.034,43.714) 58.102,43.782 58.131,43.782 59.354,42.559 v1(59.866,42.552)
XT2_OUT: U_MAIN.70 Y_XT2.3 | length 3.3
  Top w0.15: Y_XT2.3 56.4,42.715 57.591,43.906 57.591,44.653 U_MAIN.70
pads on no net: J_USB.5 J_USB.11 J_USB.NPTH-1 J_USB.NPTH-2 U_LDO.4 U_MAIN.1 U_MAIN.2 U_MAIN.3 U_MAIN.4 U_MAIN.5 U_MAIN.6 U_MAIN.7 U_MAIN.8 U_MAIN.9 U_MAIN.10 U_MAIN.12 U_MAIN.13 U_MAIN.15 U_MAIN.16 U_MAIN.17 U_MAIN.21 U_MAIN.22 U_MAIN.23 U_MAIN.25 U_MAIN.26 U_MAIN.27 U_MAIN.28 U_MAIN.29 U_MAIN.30 U_MAIN.31 U_MAIN.32 U_MAIN.33 U_MAIN.34 U_MAIN.35 U_MAIN.36 U_MAIN.39 U_MAIN.42 U_MAIN.43 U_MAIN.44 U_MAIN.45 U_MAIN.46 U_MAIN.47 U_MAIN.48 U_MAIN.51 U_MAIN.52 U_MAIN.53 U_MAIN.54 U_MAIN.55 U_MAIN.56 U_MAIN.57 U_MAIN.58 U_MAIN.59 U_MAIN.60 U_MAIN.72 U_MAIN.73 U_MAIN.74 U_MAIN.75 U_MAIN.77 U_MAIN.78 U_MAIN.79 U_MAIN.80

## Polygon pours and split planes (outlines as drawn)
GND on Bottom (solid): 107.1,77.1 25.7,77.1 25.7,25.7 107.1,25.7

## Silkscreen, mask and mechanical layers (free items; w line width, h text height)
Top Overlay:
  text "2L • BOTTOM GND POUR" at 47.4,75.4 h0.48
  text "I2C 0x76 • USB-C" at 85.4,75.4 h0.55
  text "BME280" at 88.4,28.9 h0.58
  text "QUICK CONFIGURE • SENSOR" at 66.4,27.4 h0.72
